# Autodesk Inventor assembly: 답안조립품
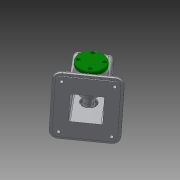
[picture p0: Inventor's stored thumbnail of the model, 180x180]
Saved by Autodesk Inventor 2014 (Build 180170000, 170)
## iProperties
Created: 2016-06
Part Number: 답안조립품
Document SubType Name: Assembly
Designer: user
Author: user
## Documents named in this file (17)
- C:\Users\user\Desktop\Manufacturing2급-박현숙\답안조립품.iam
- C:\Users\user\Desktop\Manufacturing2급-박현숙\본체.ipt
- C:\Users\user\Desktop\Manufacturing2급-박현숙\편심축.ipt
- C:\Users\user\Desktop\Manufacturing2급-박현숙\와셔.ipt
- C:\Users\user\Desktop\Manufacturing2급-박현숙\멈춤링 15 x 1.ipt
- C:\Users\user\Desktop\Manufacturing2급-박현숙\베어링 15 x 35 x 11.ipt
- C:\Users\user\Desktop\Manufacturing2급-박현숙\뒤커버.ipt
- C:\Users\user\Desktop\Manufacturing2급-박현숙\앞커버.ipt
- C:\Users\user\Desktop\Manufacturing2급-박현숙\V-벨트풀리.ipt
- C:\Users\user\Desktop\Manufacturing2급-박현숙\상부부시.ipt
- C:\Users\user\Desktop\Manufacturing2급-박현숙\슬라이드바.ipt
- C:\Users\user\Desktop\Manufacturing2급-박현숙\오일실 15 25 7.ipt
- C:\Users\user\Desktop\Manufacturing2급-박현숙\키 5 x 5 x 14.ipt
- C:\Users\user\Desktop\Manufacturing2급-박현숙\볼트 M6 x 12.ipt
- C:\Users\user\Desktop\Manufacturing2급-박현숙\고정핀.ipt
- C:\Users\user\Desktop\Manufacturing2급-박현숙\링크.ipt
- C:\Users\user\Desktop\Manufacturing2급-박현숙\멈춤링 6 x 5.ipt
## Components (3 placed, 3 different names)
1. V-벨트풀리:1 — Mate:18, Mate:19, Mate:24
2. ISO 4018 M6 x 12:1 — Mate:39, Mate:40
3. 고정핀:1 — Mate:27, Mate:28, Insert:4, Insert:5, Mate:29
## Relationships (10: Mate 8, Insert 2)
- Mate:18: V-벨트풀리:1
- Mate:19: V-벨트풀리:1
- Mate:24: V-벨트풀리:1
- Mate:27: 고정핀:1
- Mate:28: 고정핀:1
- Insert:4: 고정핀:1
- Insert:5: 고정핀:1
- Mate:29: 고정핀:1
- Mate:39: ISO 4018 M6 x 12:1
- Mate:40: ISO 4018 M6 x 12:1
